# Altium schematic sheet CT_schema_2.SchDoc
size 356 x 211 mm
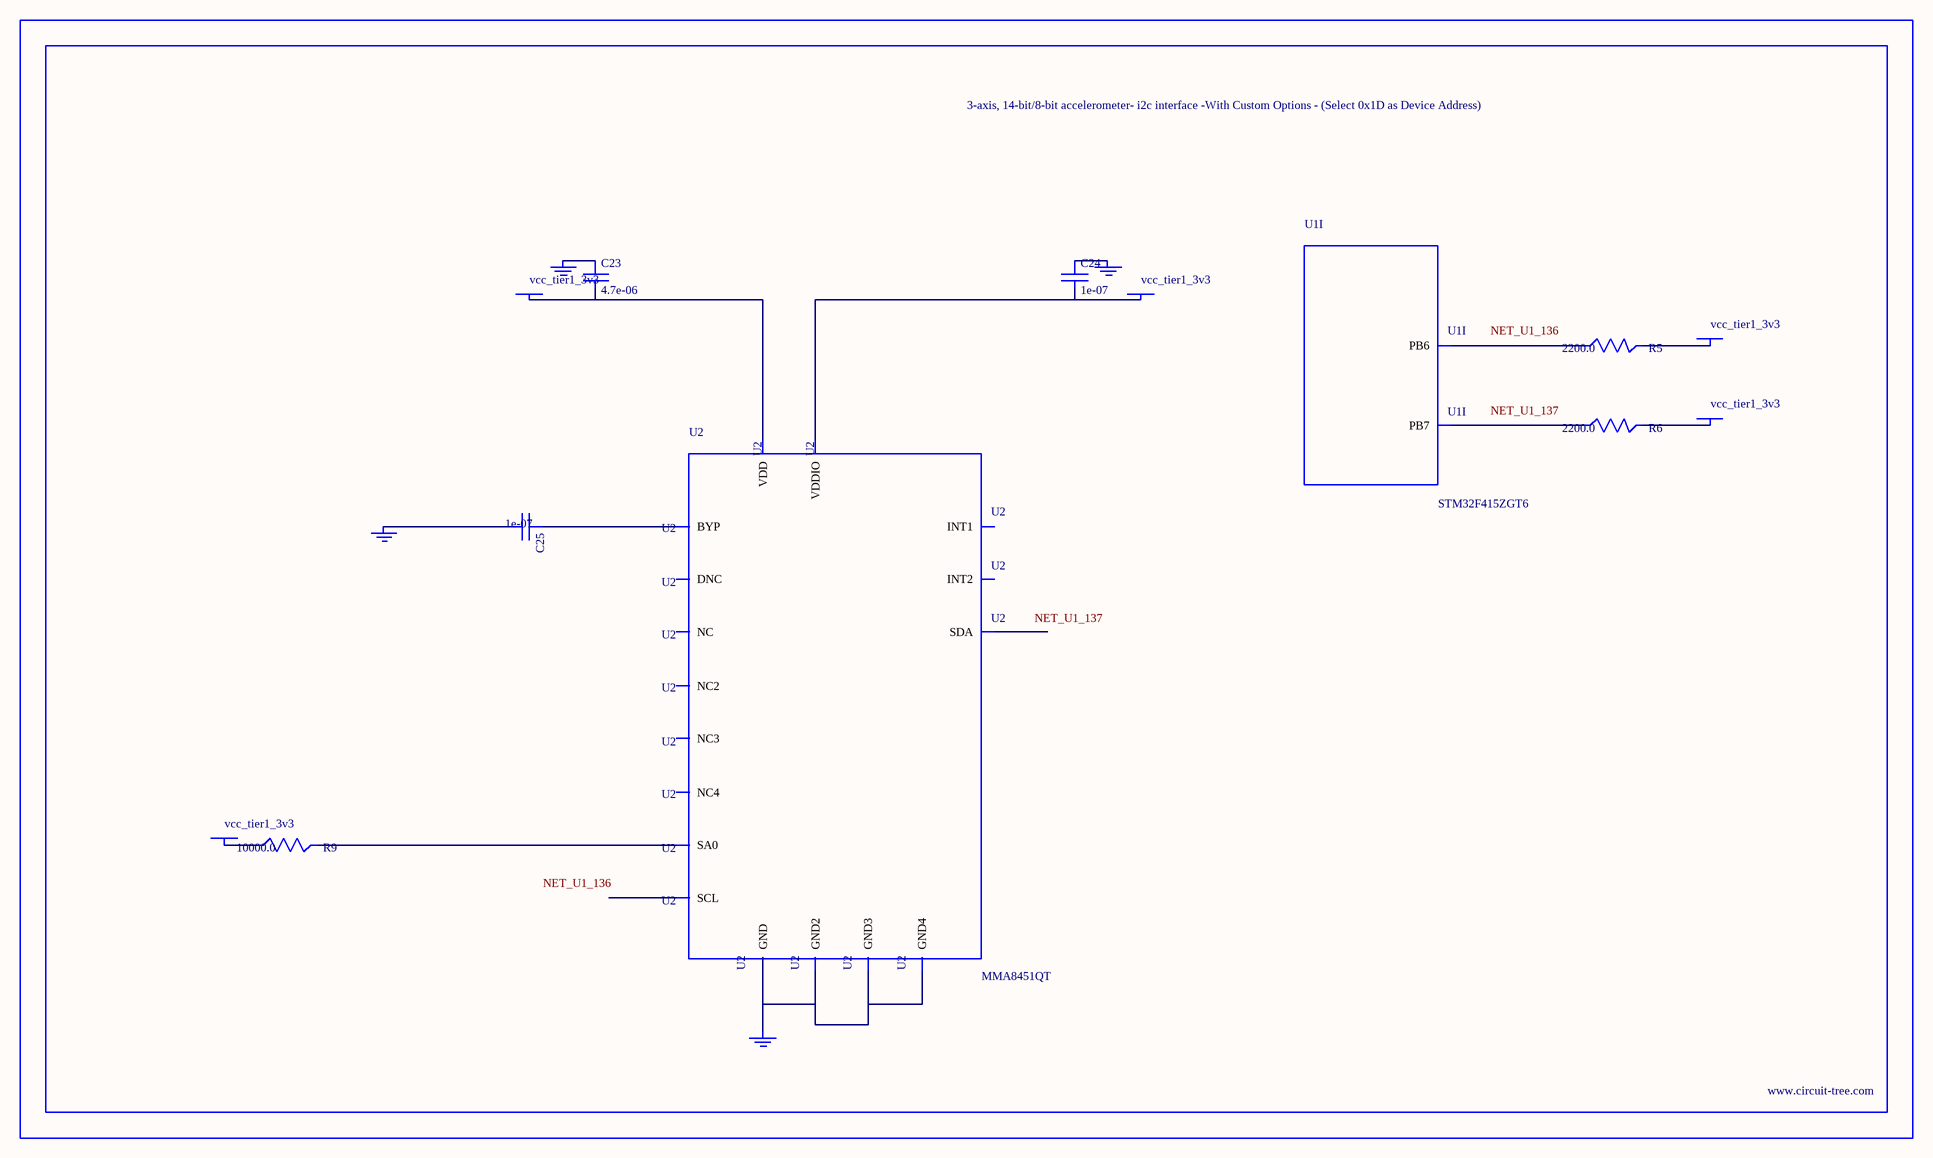
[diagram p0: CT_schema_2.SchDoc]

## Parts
BORDER1  (no value)
C23  4.7e-06  [C0805]
C24  1e-07  [C0402]
C25  1e-07  [C0402]
GND_INSTANCE_1_0  (no value)
GND_INSTANCE_1_1  (no value)
GND_INSTANCE_1_2  (no value)
GND_INSTANCE_1_3  (no value)
POWER_INSTANCE_1_0  vcc_tier1_3v3
POWER_INSTANCE_1_1  vcc_tier1_3v3
POWER_INSTANCE_1_2  vcc_tier1_3v3
POWER_INSTANCE_1_3  vcc_tier1_3v3
POWER_INSTANCE_1_4  vcc_tier1_3v3
R5  2200.0  [R0603]
R6  2200.0  [R0603]
R9  10000.0  [R0603]
U1  STM32F415ZGT6  [LQFP144]  (part I of 12)
U2  MMA8451QT  [QFN-16]

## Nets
NetC23_1: C23.1 GND_INSTANCE_1_2.0(GND)
NetC23_2: C23.2 POWER_INSTANCE_1_2.0(PWR) U2.14(VDD)
NetC24_1: C24.1 GND_INSTANCE_1_0.0(GND)
NetC24_2: C24.2 POWER_INSTANCE_1_0.0(PWR) U2.1(VDDIO)
NetC25_1: C25.1 U2.2(BYP)
NetC25_2: C25.2 GND_INSTANCE_1_1.0(GND)
NetGND_INSTANCE_1_3_0: GND_INSTANCE_1_3.0(GND) U2.5(GND) U2.10(GND2) U2.12(GND3) U2.17(GND4)
NetPOWER_INSTANCE_1_1_0: POWER_INSTANCE_1_1.0(PWR) R9.1
NetPOWER_INSTANCE_1_3_0: POWER_INSTANCE_1_3.0(PWR) R5.2
NetPOWER_INSTANCE_1_4_0: POWER_INSTANCE_1_4.0(PWR) R6.2
NetR5_1: R5.1 U1.136(PB6)
NetR6_1: R6.1 U1.137(PB7)
NetR9_2: R9.2 U2.7(SA0)

Not connected (* = marked no-connect by the designer): U2 3(DNC) 4(SCL) 6(SDA) 8(NC) 9(INT2) 11(INT1) 13(NC2) 15(NC3) 16(NC4)

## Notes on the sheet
- Labels drawn without touching a wire or pin: NET_U1_136, NET_U1_137

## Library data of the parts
BORDER1 = BORDER_PAGE1
C23 = C0805C475K4RACTU
C24 C25 = C0402C104K3RACTU
GND_INSTANCE_1_0-GND_INSTANCE_1_3 = GND
POWER_INSTANCE_1_0-POWER_INSTANCE_1_4 = PWR
R5 R6 = RC0603JR-072K2L
R9 = RC0603JR-0710KL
